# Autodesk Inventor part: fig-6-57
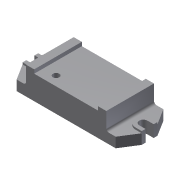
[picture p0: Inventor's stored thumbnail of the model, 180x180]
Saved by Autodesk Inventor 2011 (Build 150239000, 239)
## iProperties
Shininess: 77.0
Angle Display Precision: 2
Document Length Units: 11269
Document Angle Units: 11279
Document Time Units: 11290
Document Mass Units: 11283
Document Length Units Precision: 3
Document Angle Units Precision: 2
Created: 2001-12
Part Number: fig-6-57
Document SubType Name: Modeling
Designer: Renu Muthoo
Density: 1 g/cm^3
Density: 0.0
Volumn: 0.0
Area: 0.0
PropertySet Name: Model Information
Control State: 0
Master: False
Checked Out: False
Author: Renu Muthoo
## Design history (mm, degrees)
sketch "Sketch3"
  geometry: L1 (-59.119, -24.322)-(-59.119, 19.678); L2 (-59.119, 19.678)-(-46.119, 19.678); L3 (-46.119, 19.678)-(-46.119, 13.678); L4 (-46.119, 13.678)-(55.881, 13.678); L5 (55.881, 13.678)-(55.881, 19.678); L6 (55.881, 19.678)-(68.881, 19.678); L7 (68.881, 19.678)-(68.881, -24.322); L8 (68.881, -24.322)-(-59.119, -24.322)
  constraints: 16 end point, 2 equal length
  dimensions: "d10" = 13 distance of L1.end L2.end; "d11" = 102 distance of L3.end L4.end; "d13" = 44 distance between parallel lines of L2 L8; "d14" = 6 distance of L2.end L3.end
extrude "Extrusion1" new body sketch "Sketch3" distance "d15" = 76; taper "d16" = 0 deg
sketch "Sketch4"
  geometry: L1 (0, 0)-(0, 76) reference; L2 (0, 76)-(-15, 76); L3 (-15, 76)-(-31, 50.5); L4 (-31, 50.5)-(-31, 44.5); L5 (-31, 44.5)-(-21, 44.5); L6 (-21, 31.5)-(-31, 31.5); L7 (-31, 31.5)-(-31, 25.5); L8 (-31, 25.5)-(-15, 0); L9 (-15, 0)-(0, 0); L10 (128, 76)-(0, 76) reference; L11 (0, 0)-(128, 0) reference; A1 r 6.5 centre (-21, 38) between (-21, 31.5) and (-21, 44.5)
  constraints: 16 end point, 4 equal length, 3 collinear, 3 parallel, 2 perpendicular, 2 point on circle, 2 tangent, 1 centre point
  dimensions: "d17" = 13 distance between parallel lines of L6 L5; "d18" = 25 distance of L3.end L7.end; "d19" = 10 distance of L6.start L6.end; "d20" = 15 distance of L8.end L1.start; "d21" = 16 horizontal distance of L7.end L8.end
extrude "Extrusion2" join sketch "Sketch4" distance "d22" = 16; taper "d23" = 0 deg
sketch "Sketch5"
  geometry: L1 (-159, 44.5)-(-159, 50.5) reference; L2 (-149, 44.5)-(-159, 44.5) reference; L3 (-159, 31.5)-(-149, 31.5) reference; L4 (-159, 25.5)-(-159, 31.5) reference; L5 (-159, 25.5)-(-149, 25.5); L6 (-149, 50.5)-(-159, 50.5); A1 r 6.5 centre (-149, 38) between (-149, 31.5) and (-149, 44.5) reference; A2 r 12.5 centre (-149, 38) between (-149, 25.5) and (-149, 50.5)
  constraints: 4 end point, 2 point on circle, 2 tangent, 1 centre point, 1 parallel, 1 perpendicular
extrude "Extrusion3" join sketch "Sketch5" distance "d24" = 19; taper "d25" = 0 deg
workplane "Work Plane1"
mirror "Mirror1"
fillet "Fillet1" dims "d27" = 4
sketch "Sketch6"
  geometry: L1 (0, 0)-(0, 76) reference; L2 (0, 0)-(102, 0) reference; 1 further point
  dimensions: "d28" = 20 distance from line of L1 point (20, 15); "d29" = 15 distance from line of L2 point (20, 15)
hole "Hole1" sketch "Sketch6" at (20, 15) diameter "d30" = 10; stored, may be unused: countersink angle "d34" = 82 deg, drill point angle "d36" = 118 deg; dims "d31" = 6, "d32" = 4, "d33" = 2, "d35" = 15
sketch "Sketch7"
  geometry: C1 r 5 at (20, 15) reference; 3 further points
  constraints: 4 other
body "Solid1"
other parameters: "d26" = -64
